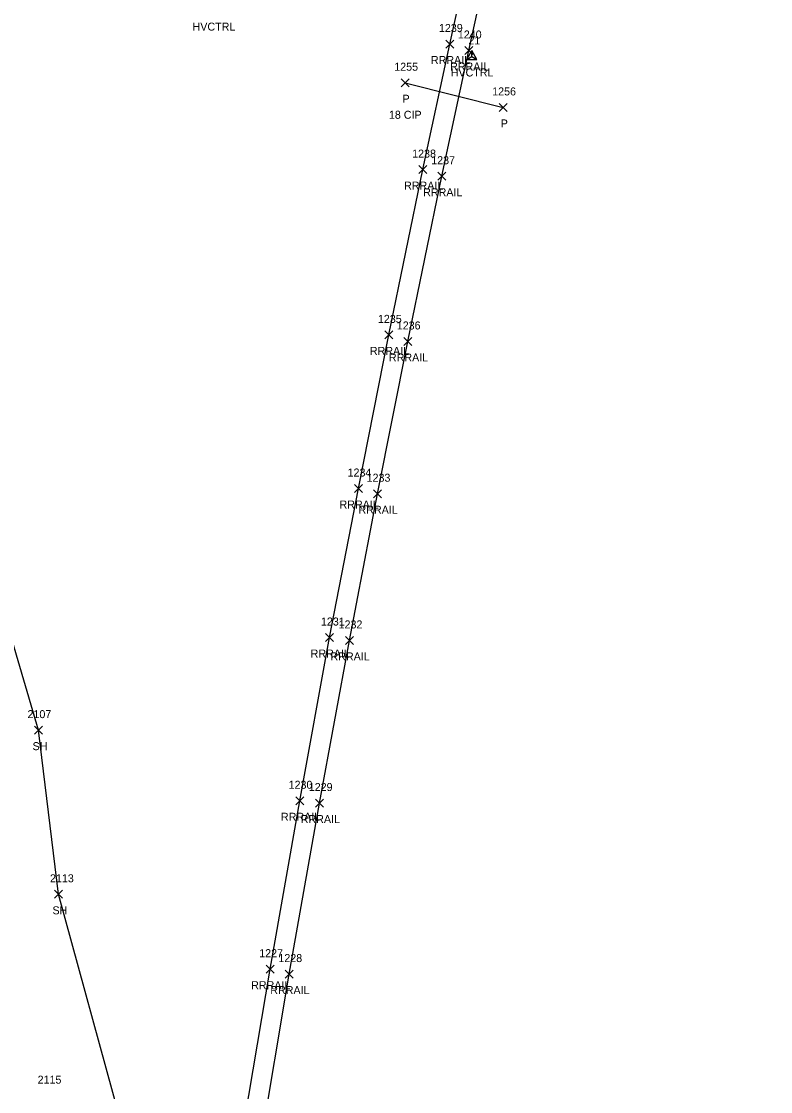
# Model space of a CAD drawing. Extents: x 1754529 to 1755810, y 621660 to 624656.
# Drawn here: x 1755617.5 to 1755804.8, y 624067.2 to 624334.6 of the extents above; entities that cross this region are included whole.
import ezdxf

# ---------------------------------------------------------------- set-up
doc = ezdxf.new("R2010")
doc.units = 0
for name, color, linetype in [('C_A', 7, 'Continuous'), ('C_I', 7, 'Continuous'), ('CPSM', 7, 'Continuous'), ('D_A', 7, 'Continuous'), ('D_C', 7, 'Continuous'), ('D_I', 7, 'Continuous'), ('D_TIC', 7, 'Continuous'), ('DCP', 7, 'Continuous'), ('L_A', 7, 'Continuous'), ('L_I', 7, 'Continuous'), ('L_TIC', 7, 'Continuous'), ('LSOGP', 7, 'Continuous'), ('R_A', 7, 'Continuous'), ('R_I', 7, 'Continuous'), ('R_TIC', 7, 'Continuous'), ('RR', 7, 'Continuous')]:
    doc.layers.add(name, color=color, linetype=linetype)

msp = doc.modelspace()

# ---------------------------------------------------------------- linework, layer by layer
at = {"layer": 'CPSM'}
for p, q in [((1755728.86, 624325.08), (1755730.11, 624327.25)), ((1755728.86, 624325.08), (1755730.11, 624325.8)), ((1755731.36, 624325.08), (1755730.11, 624327.25)), ((1755730.11, 624325.8), (1755730.11, 624327.25)), ((1755730.11, 624325.8), (1755730.11, 624325.8)), ((1755730.11, 624325.8), (1755731.36, 624325.08)), ((1755728.86, 624325.08), (1755731.36, 624325.08))]:
    msp.add_line(p, q, dxfattribs=at)
at = {"layer": 'D_TIC'}
for points in [[(1755712.38, 624318.23), (1755714.38, 624320.23)], [(1755714.38, 624318.23), (1755712.38, 624320.23)], [(1755736.92, 624312.06), (1755738.92, 624314.06)], [(1755738.92, 624312.06), (1755736.92, 624314.06)]]:
    msp.add_lwpolyline(points, dxfattribs=at)
at = {"layer": 'DCP'}
msp.add_lwpolyline([(1755713.38, 624319.23), (1755737.92, 624313.06)], dxfattribs=at)
at = {"layer": 'L_TIC'}
for points in [[(1755620.8, 624156.48), (1755622.8, 624158.48)], [(1755622.8, 624156.48), (1755620.8, 624158.48)], [(1755625.78, 624115.47), (1755627.78, 624117.47)], [(1755627.78, 624115.47), (1755625.78, 624117.47)]]:
    msp.add_lwpolyline(points, dxfattribs=at)
at = {"layer": 'LSOGP'}
msp.add_lwpolyline([(1755642.06, 624060.86), (1755626.78, 624116.47), (1755621.8, 624157.48), (1755611.99, 624190.67), (1755601.72, 624203.48), (1755602.4, 624225.76), (1755604.25, 624255.82), (1755611.46, 624290.08), (1755601.72, 624293.11), (1755598.86, 624293.76), (1755597.12, 624294.33), (1755583.45, 624297.71), (1755570.27, 624301.63), (1755569.13, 624303.44), (1755566.56, 624304.36), (1755564.22, 624305.05), (1755561.77, 624305.07), (1755551.47, 624255.48), (1755539.26, 624211.65), (1755530.35, 624173.06), (1755439.25, 624209.67), (1755429.39, 624262.07), (1755437.36, 624304.76), (1755388.37, 624309.67)], dxfattribs=at)
at = {"layer": 'R_TIC'}
for points in [[(1755723.56, 624327.91), (1755725.56, 624329.91)], [(1755725.56, 624327.91), (1755723.56, 624329.91)], [(1755728.35, 624326.29), (1755730.35, 624328.29)], [(1755730.35, 624326.29), (1755728.35, 624328.29)], [(1755716.86, 624296.53), (1755718.86, 624298.53)], [(1755718.86, 624296.53), (1755716.86, 624298.53)], [(1755721.62, 624294.88), (1755723.62, 624296.88)], [(1755723.62, 624294.88), (1755721.62, 624296.88)], [(1755708.31, 624255.23), (1755710.31, 624257.23)], [(1755710.31, 624255.23), (1755708.31, 624257.23)], [(1755713.07, 624253.59), (1755715.07, 624255.59)], [(1755715.07, 624253.59), (1755713.07, 624255.59)], [(1755700.72, 624216.85), (1755702.72, 624218.85)], [(1755702.72, 624216.85), (1755700.72, 624218.85)], [(1755705.47, 624215.55), (1755707.47, 624217.55)], [(1755707.47, 624215.55), (1755705.47, 624217.55)], [(1755693.5, 624179.62), (1755695.5, 624181.62)], [(1755695.5, 624179.62), (1755693.5, 624181.62)], [(1755698.47, 624178.9), (1755700.47, 624180.9)], [(1755700.47, 624178.9), (1755698.47, 624180.9)], [(1755686.07, 624138.84), (1755688.07, 624140.84)], [(1755688.07, 624138.84), (1755686.07, 624140.84)], [(1755691.03, 624138.27), (1755693.03, 624140.27)], [(1755693.03, 624138.27), (1755691.03, 624140.27)], [(1755678.64, 624096.76), (1755680.64, 624098.76)], [(1755680.64, 624096.76), (1755678.64, 624098.76)], [(1755683.42, 624095.54), (1755685.42, 624097.54)], [(1755685.42, 624095.54), (1755683.42, 624097.54)]]:
    msp.add_lwpolyline(points, dxfattribs=at)
at = {"layer": 'RR'}
for points in [[(1755627.39, 623699.11), (1755631.78, 623745.19), (1755637.11, 623795.68), (1755642.45, 623841.98), (1755647.89, 623885.58), (1755654.04, 623931.54), (1755660.61, 623977.9), (1755666.29, 624016.06), (1755672.3, 624053.9), (1755679.64, 624097.76), (1755687.07, 624139.84), (1755694.5, 624180.62), (1755701.72, 624217.85), (1755709.31, 624256.23), (1755717.86, 624297.53), (1755724.56, 624328.91), (1755733.93, 624371.3), (1755743.26, 624412.4), (1755753.41, 624456.24), (1755764.06, 624501.26), (1755774.99, 624547.18), (1755787.52, 624599.52), (1755800.05, 624650.73)], [(1755632.43, 623698.79), (1755636.73, 623745.2), (1755642.03, 623795.46), (1755647.4, 623842), (1755652.81, 623884.87), (1755658.94, 623931.22), (1755665.5, 623977.61), (1755671.13, 624015.19), (1755677.17, 624053.23), (1755684.42, 624096.54), (1755692.03, 624139.27), (1755699.47, 624179.9), (1755706.47, 624216.55), (1755714.07, 624254.59), (1755722.62, 624295.88), (1755729.35, 624327.29), (1755738.69, 624369.66), (1755747.98, 624411.22), (1755758.14, 624454.7), (1755769.01, 624500.51), (1755779.76, 624545.7), (1755792.4, 624598.28), (1755804.75, 624649.74)]]:
    msp.add_lwpolyline(points, dxfattribs=at)

# ---------------------------------------------------------------- texts
at = {"layer": 'C_A'}
for p in [(1755660.28, 624332.25), (1755724.8, 624320.8)]:
    msp.add_text('HVCTRL', height=2, dxfattribs=at).set_placement(p)
at = {"layer": 'C_I'}
msp.add_text('21', height=2, dxfattribs=at).set_placement((1755729.21, 624328.8))
at = {"layer": 'D_A'}
for p in [(1755712.76, 624314.23), (1755737.3, 624308.06)]:
    msp.add_text('P', height=2, dxfattribs=at).set_placement(p)
at = {"layer": 'D_C'}
msp.add_text('18 CIP', height=2, dxfattribs=at).set_placement((1755709.36, 624310.23))
at = {"layer": 'D_I'}
for s, p in [('1255', (1755710.69, 624322.23)), ('1256', (1755735.17, 624316.06))]:
    msp.add_text(s, height=2, dxfattribs=at).set_placement(p)
at = {"layer": 'L_A'}
for p in [(1755620.29, 624152.48), (1755625.27, 624111.47)]:
    msp.add_text('SH', height=2, dxfattribs=at).set_placement(p)
at = {"layer": 'L_I'}
for s, p in [('2107', (1755619.03, 624160.48)), ('2113', (1755624.65, 624119.47)), ('2115', (1755621.55, 624069.15))]:
    msp.add_text(s, height=2, dxfattribs=at).set_placement(p)
at = {"layer": 'R_A'}
for p in [(1755719.85, 624323.91), (1755724.65, 624322.29), (1755713.15, 624292.53), (1755717.92, 624290.88), (1755704.6, 624251.23), (1755709.36, 624249.59), (1755697.01, 624212.85), (1755701.76, 624211.55), (1755689.79, 624175.62), (1755694.76, 624174.9), (1755682.37, 624134.84), (1755687.32, 624134.27), (1755674.93, 624092.76), (1755679.71, 624091.54)]:
    msp.add_text('RRRAIL', height=2, dxfattribs=at).set_placement(p)
at = {"layer": 'R_I'}
for s, p in [('1239', (1755721.86, 624331.91)), ('1240', (1755726.58, 624330.29)), ('1238', (1755715.17, 624300.53)), ('1237', (1755719.93, 624298.88)), ('1235', (1755706.61, 624259.23)), ('1236', (1755711.32, 624257.59)), ('1234', (1755699.03, 624220.85)), ('1233', (1755703.78, 624219.55)), ('1231', (1755692.37, 624183.62)), ('1232', (1755696.78, 624182.9)), ('1230', (1755684.29, 624142.84)), ('1229', (1755689.32, 624142.27)), ('1227', (1755676.94, 624100.76)), ('1228', (1755681.73, 624099.54))]:
    msp.add_text(s, height=2, dxfattribs=at).set_placement(p)

doc.saveas('drawing.dxf')
